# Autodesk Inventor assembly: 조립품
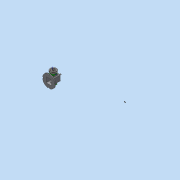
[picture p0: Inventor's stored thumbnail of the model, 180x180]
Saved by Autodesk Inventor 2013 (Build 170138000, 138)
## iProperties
Created: 2018-07
Part Number: 조립품
Document SubType Name: Assembly
Designer: dgall
Author: dgall
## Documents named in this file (16)
- C:\Users\dgall\Desktop\480707V1017\조립품.iam
- C:\Users\dgall\Desktop\480707V1017\본체.ipt
- C:\Users\dgall\Desktop\480707V1017\멈춤나사 M3x8.ipt
- C:\Users\dgall\Desktop\480707V1017\볼트 M4 x 12.ipt
- C:\Users\dgall\Desktop\480707V1017\뒤커버.ipt
- C:\Users\dgall\Desktop\480707V1017\앞커버.ipt
- C:\Users\dgall\Desktop\480707V1017\오일 실 12 25 7.ipt
- C:\Users\dgall\Desktop\480707V1017\키 4x4x10.ipt
- C:\Users\dgall\Desktop\480707V1017\편심축.ipt
- C:\Users\dgall\Desktop\480707V1017\슬라이드.ipt
- C:\Users\dgall\Desktop\480707V1017\부시.ipt
- C:\Users\dgall\Desktop\480707V1017\링크.ipt
- C:\Users\dgall\Desktop\480707V1017\베어링 12x32x10.ipt
- C:\Users\dgall\Desktop\480707V1017\V벨트풀리 (2).ipt
- C:\Users\dgall\Desktop\480707V1017\핀 5x18.ipt
- C:\Users\dgall\Desktop\480707V1017\볼트 M4.ipt
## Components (2 placed, 2 different names)
1. V벨트풀리 (2):1
2. 핀 5x18:1
